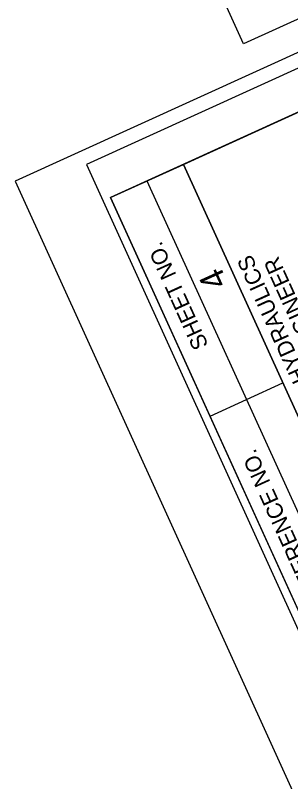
# Model space of a CAD drawing. Extents: x 2097304 to 2099003, y 683920 to 685908.
# Drawn here: x 2097304.4 to 2097390.4, y 685265 to 685504.5 of the extents above; entities that cross this region are included whole.
import ezdxf

# ---------------------------------------------------------------- set-up
doc = ezdxf.new("R2010")
doc.units = 0
for name, color, linetype in [('Sheet Data Field CELL', 7, 'Continuous'), ('Sheet Plot Border Inside CELL', 7, 'Continuous'), ('Sheet Plot Border Outside CELL', 7, 'Continuous'), ('Sheet Profile CELL', 7, 'Continuous'), ('Sheet Sticker Incomplete CELL', 7, 'Continuous')]:
    doc.layers.add(name, color=color, linetype=linetype)

msp = doc.modelspace()

# ---------------------------------------------------------------- linework, layer by layer
at = {"layer": 'Sheet Plot Border Inside CELL'}
msp.add_lwpolyline([(2098977.25, 684378), (2098287.02, 685894.84), (2097326.67, 685457.85), (2098016.9, 683941)], close=True, dxfattribs=at)
at = {"layer": 'Sheet Plot Border Outside CELL'}
msp.add_lwpolyline([(2099003.07, 684375.47), (2098305.59, 685908.24), (2097304.38, 685452.65), (2098001.85, 683919.87)], close=True, dxfattribs=at)
at = {"layer": 'Sheet Profile CELL'}
for p, q in [((2097428.45, 685270.64), (2097345.6, 685452.72)), ((2097365.28, 685379.28), (2097388.04, 685389.64))]:
    msp.add_line(p, q, dxfattribs=at)
for points in [[(2097334.17, 685447.53), (2097955.44, 684082.23), (2098911.14, 684517.12), (2098289.88, 685882.41)], [(2097398.39, 685366.88), (2097356.97, 685457.9), (2097459.37, 685504.5), (2097500.79, 685413.48)], [(2097417.03, 685265.44), (2097334.17, 685447.53), (2097356.97, 685457.9), (2097439.83, 685275.82)]]:
    msp.add_lwpolyline(points, close=True, dxfattribs=at)
at = {"layer": 'Sheet Sticker Incomplete CELL'}
msp.add_lwpolyline([(2097397.1, 685505.3), (2097375.71, 685495.56), (2097314.83, 685629.36), (2097336.22, 685639.1)], close=True, dxfattribs=at)

# ---------------------------------------------------------------- texts
at = {"layer": 'Sheet Data Field CELL'}
msp.add_text('4', height=7.75, rotation=114.4674, dxfattribs=at).set_placement((2097370.88, 685420.9))
at = {"layer": 'Sheet Profile CELL'}
for s, height, p in [('SHEET NO.', 5, (2097364.82, 685401.39)), ('HYDRAULICS', 5, (2097395.94, 685390.83)), ('ENGINEER', 5, (2097400.87, 685397.74)), ('PROJECT REFERENCE NO.', 5.0001, (2097415.74, 685289.26))]:
    msp.add_text(s, height=height, rotation=114.4674, dxfattribs=at).set_placement(p)

doc.saveas('drawing.dxf')
